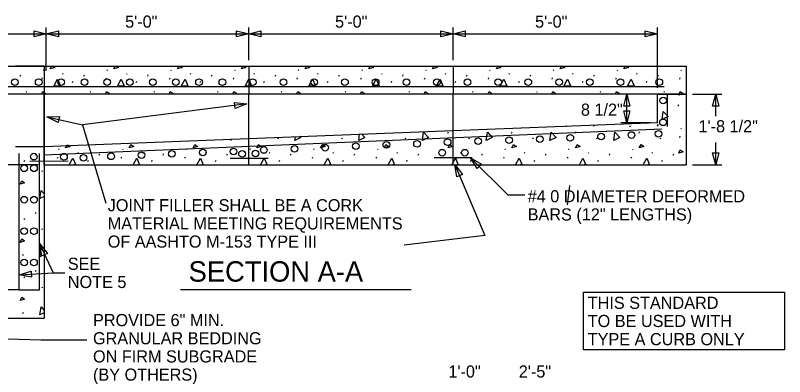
# Model space of a CAD drawing. Extents: x 100.2 to 136.1, y 126.8 to 178.4.
# Drawn here: x 116.67 to 135.49, y 144.43 to 153.28 of the extents above; entities that cross this region are included whole.
import ezdxf

# ---------------------------------------------------------------- set-up
doc = ezdxf.new("R2010")
doc.units = 0
for name, color, linetype in [('DETL-DIMS', 7, 'Continuous'), ('DETL-LINE', 7, 'Continuous'), ('DETL-NOTE', 7, 'Continuous'), ('DETL-PATT', 7, 'Continuous')]:
    doc.layers.add(name, color=color, linetype=linetype)

msp = doc.modelspace()

# ---------------------------------------------------------------- linework, layer by layer
at = {"layer": 'DETL-DIMS'}
for p, q in [((117.428, 151.919), (117.428, 152.978)), ((122.381, 152.183), (122.381, 152.978)), ((127.381, 152.183), (127.381, 152.978)), ((132.381, 151.501), (132.381, 152.978)), ((112.381, 152.83), (117.428, 152.83)), ((117.428, 152.83), (122.381, 152.83)), ((122.381, 152.83), (127.381, 152.83)), ((127.381, 152.83), (132.381, 152.83)), ((132.233, 151.353), (131.485, 151.353)), ((131.633, 150.644), (131.633, 151.353)), ((133.237, 151.353), (133.956, 151.353)), ((133.808, 150.813), (133.808, 151.353)), ((122.337, 151.11), (118.312, 150.596)), ((132.233, 150.644), (131.485, 150.644)), ((133.808, 149.618), (133.808, 150.165)), ((117.233, 149.618), (115.965, 149.618)), ((133.237, 149.618), (133.956, 149.618)), ((117.597, 146.977), (117.882, 146.977))]:
    msp.add_line(p, q, dxfattribs=at)
for points in [[(117.131, 152.904), (117.428, 152.83), (117.131, 152.756)], [(117.725, 152.756), (117.428, 152.83), (117.725, 152.904)], [(122.084, 152.904), (122.381, 152.83), (122.084, 152.756)], [(122.678, 152.756), (122.381, 152.83), (122.678, 152.904)], [(127.084, 152.904), (127.381, 152.83), (127.084, 152.756)], [(127.678, 152.756), (127.381, 152.83), (127.678, 152.904)], [(132.084, 152.904), (132.381, 152.83), (132.084, 152.756)], [(131.559, 151.056), (131.633, 151.353), (131.707, 151.056)], [(133.734, 151.056), (133.808, 151.353), (133.882, 151.056)], [(122.034, 151.145), (122.337, 151.11), (122.052, 150.999)], [(117.717, 150.656), (117.444, 150.794), (117.75, 150.8)], [(131.707, 150.941), (131.633, 150.644), (131.559, 150.941)], [(133.882, 149.915), (133.808, 149.618), (133.734, 149.915)], [(127.969, 149.53), (127.811, 149.793), (128.074, 149.635)], [(127.475, 149.326), (127.429, 149.629), (127.612, 149.384)], [(117.324, 147.389), (117.267, 147.69), (117.459, 147.451)], [(117.067, 146.869), (116.766, 146.925), (117.057, 147.017)]]:
    msp.add_lwpolyline(points, close=True, dxfattribs=at)
for points in [[(117.444, 150.794), (118.312, 150.596), (118.884, 148.681)], [(127.811, 149.793), (128.721, 148.882), (129.137, 148.882)], [(127.429, 149.629), (128.159, 147.891), (126.185, 147.654)], [(117.267, 147.69), (117.597, 146.977)], [(116.766, 146.925), (117.597, 146.977)], [(113.046, 145.468), (117.297, 145.338), (118.42, 145.338)]]:
    msp.add_lwpolyline(points, dxfattribs=at)
at = {"layer": 'DETL-LINE'}
for p, q in [((112.381, 152.035), (117.381, 152.035)), ((117.381, 152.035), (116.673, 152.035)), ((117.381, 152.035), (133.089, 152.035)), ((117.381, 152.035), (117.381, 151.353)), ((122.381, 152.035), (122.381, 151.353)), ((127.381, 152.035), (127.381, 151.353)), ((133.089, 152.035), (133.089, 149.618)), ((132.549, 151.53), (111.98, 151.53)), ((133.089, 151.353), (111.673, 151.353)), ((117.381, 149.618), (117.381, 151.353)), ((122.381, 149.618), (122.381, 151.353)), ((127.381, 149.618), (127.381, 151.353)), ((132.381, 150.644), (132.381, 151.353)), ((132.381, 151.353), (133.089, 151.353)), ((132.571, 151.353), (133.089, 151.353)), ((132.632, 150.554), (132.632, 151.351)), ((132.381, 150.644), (117.381, 150.063)), ((117.37, 149.867), (132.492, 150.503)), ((117.381, 150.063), (116.673, 150.063)), ((116.766, 146.555), (116.765, 149.893)), ((117.267, 146.555), (117.267, 149.893)), ((117.03, 149.709), (117.963, 149.716)), ((121.926, 149.78), (122.859, 149.78)), ((126.918, 149.803), (127.851, 149.803)), ((117.381, 149.618), (133.089, 149.618)), ((116.766, 146.555), (112.331, 146.555)), ((116.766, 146.555), (117.267, 146.555)), ((111.673, 145.864), (117.381, 145.864))]:
    msp.add_line(p, q, dxfattribs=at)
msp.add_lwpolyline([(111.673, 145.864), (111.673, 152.035), (117.381, 152.035), (117.381, 145.864)], dxfattribs=at)
for centre in [(116.657, 151.644), (117.243, 151.644), (117.792, 151.644), (118.362, 151.644), (118.918, 151.644), (119.475, 151.644), (120.037, 151.644), (120.601, 151.644), (121.166, 151.644), (121.737, 151.644), (122.479, 151.644), (123.232, 151.644), (123.984, 151.644), (124.737, 151.644), (125.488, 151.644), (126.241, 151.644), (126.988, 151.644), (127.737, 151.644), (128.487, 151.644), (129.223, 151.644), (129.979, 151.644), (130.728, 151.644), (131.476, 151.644), (132.429, 151.644), (132.525, 151.196), (132.52, 150.66), (131.003, 150.313), (131.749, 150.349), (132.409, 150.38), (126.5, 150.136), (127.25, 150.173), (127.997, 150.201), (128.752, 150.222), (129.504, 150.25), (130.251, 150.282), (122.01, 149.946), (122.75, 149.983), (123.504, 150.011), (124.251, 150.039), (125.002, 150.075), (125.751, 150.107), (117.122, 149.82), (117.862, 149.818), (118.341, 149.793), (119.013, 149.828), (119.758, 149.858), (120.501, 149.89), (121.257, 149.922), (122.219, 149.887), (122.55, 149.898), (127.115, 149.917), (127.671, 149.917), (116.889, 149.535), (117.128, 149.535), (116.889, 148.766), (117.128, 148.766), (116.889, 147.997), (117.128, 147.997), (116.889, 147.227), (117.128, 147.227)]:
    msp.add_circle(centre, 0.0814, dxfattribs=at)
at = {"layer": 'DETL-NOTE'}
for p, q in [((130.179, 148.644), (130.241, 149.112)), ((120.711, 146.571), (126.36, 146.571))]:
    msp.add_line(p, q, dxfattribs=at)
msp.add_lwpolyline([(130.573, 146.503), (135.495, 146.503), (135.495, 145.089), (130.573, 145.089)], close=True, dxfattribs=at)
at = {"layer": 'DETL-PATT'}
for p, q in [((117.354, 151.946), (117.366, 151.927)), ((118.914, 151.946), (118.926, 151.927)), ((120.474, 151.946), (120.486, 151.927)), ((122.034, 151.946), (122.046, 151.927)), ((123.594, 151.946), (123.606, 151.927)), ((125.154, 151.946), (125.166, 151.927)), ((126.714, 151.946), (126.726, 151.927)), ((128.274, 151.946), (128.286, 151.927)), ((129.834, 151.946), (129.846, 151.927)), ((131.394, 151.946), (131.406, 151.927)), ((132.954, 151.946), (132.966, 151.927)), ((116.79, 151.792), (116.805, 151.822)), ((117.327, 151.715), (117.339, 151.746)), ((117.828, 151.857), (117.843, 151.838)), ((118.35, 151.792), (118.365, 151.822)), ((118.887, 151.715), (118.899, 151.746)), ((119.388, 151.857), (119.403, 151.838)), ((119.91, 151.792), (119.925, 151.822)), ((120.447, 151.715), (120.459, 151.746)), ((120.948, 151.857), (120.963, 151.838)), ((121.47, 151.792), (121.485, 151.822)), ((122.007, 151.715), (122.019, 151.746)), ((122.508, 151.857), (122.523, 151.838)), ((123.03, 151.792), (123.045, 151.822)), ((123.567, 151.715), (123.579, 151.746)), ((124.068, 151.857), (124.083, 151.838)), ((124.59, 151.792), (124.605, 151.822)), ((125.127, 151.715), (125.139, 151.746)), ((125.628, 151.857), (125.643, 151.838)), ((126.15, 151.792), (126.165, 151.822)), ((126.687, 151.715), (126.699, 151.746)), ((127.188, 151.857), (127.203, 151.838)), ((127.71, 151.792), (127.725, 151.822)), ((128.247, 151.715), (128.259, 151.746)), ((128.748, 151.857), (128.763, 151.838)), ((129.27, 151.792), (129.285, 151.822)), ((129.807, 151.715), (129.819, 151.746)), ((130.308, 151.857), (130.323, 151.838)), ((130.83, 151.792), (130.845, 151.822)), ((131.367, 151.715), (131.379, 151.746)), ((131.868, 151.857), (131.883, 151.838)), ((132.39, 151.792), (132.405, 151.822)), ((132.927, 151.715), (132.939, 151.746)), ((118.072, 151.638), (118.087, 151.669)), ((119.632, 151.638), (119.647, 151.669)), ((121.192, 151.638), (121.207, 151.669)), ((122.752, 151.638), (122.767, 151.669)), ((124.312, 151.638), (124.327, 151.669)), ((125.872, 151.638), (125.887, 151.669)), ((127.432, 151.638), (127.447, 151.669)), ((128.992, 151.638), (129.007, 151.669)), ((130.552, 151.638), (130.567, 151.669)), ((132.112, 151.638), (132.127, 151.669)), ((116.94, 151.418), (116.956, 151.395)), ((118.5, 151.418), (118.516, 151.395)), ((120.06, 151.418), (120.076, 151.395)), ((121.62, 151.418), (121.636, 151.395)), ((123.18, 151.418), (123.196, 151.395)), ((124.74, 151.418), (124.756, 151.395)), ((126.3, 151.418), (126.316, 151.395)), ((127.86, 151.418), (127.876, 151.395)), ((129.42, 151.418), (129.436, 151.395)), ((130.98, 151.418), (130.996, 151.395)), ((132.54, 151.418), (132.556, 151.395)), ((132.888, 151.089), (132.892, 151.058)), ((131.704, 150.578), (131.708, 150.547)), ((125.695, 150.393), (125.697, 150.397)), ((127.255, 150.393), (127.267, 150.424)), ((128.815, 150.393), (128.827, 150.424)), ((130.147, 150.562), (130.148, 150.547)), ((130.375, 150.393), (130.387, 150.424)), ((131.935, 150.393), (131.947, 150.424)), ((132.954, 150.521), (132.966, 150.502)), ((123.097, 150.253), (123.108, 150.284)), ((124.657, 150.253), (124.668, 150.284)), ((126.217, 150.253), (126.228, 150.284)), ((127.777, 150.253), (127.788, 150.284)), ((129.337, 150.253), (129.348, 150.284)), ((130.897, 150.253), (130.908, 150.284)), ((132.457, 150.253), (132.468, 150.284)), ((132.927, 150.29), (132.939, 150.321)), ((117.166, 149.855), (117.181, 149.886)), ((117.73, 150.01), (117.742, 149.991)), ((118.204, 149.921), (118.22, 149.902)), ((118.726, 149.855), (118.741, 149.886)), ((119.29, 150.01), (119.302, 149.991)), ((119.764, 149.921), (119.78, 149.902)), ((120.286, 149.855), (120.301, 149.886)), ((120.85, 150.01), (120.862, 149.991)), ((121.324, 149.921), (121.34, 149.902)), ((121.846, 149.855), (121.861, 149.886)), ((122.41, 150.01), (122.422, 149.991)), ((122.884, 149.921), (122.9, 149.902)), ((123.406, 149.855), (123.421, 149.886)), ((123.97, 150.01), (123.982, 149.991)), ((124.444, 149.921), (124.46, 149.902)), ((124.966, 149.855), (124.981, 149.886)), ((125.53, 150.01), (125.542, 149.991)), ((126.004, 149.921), (126.02, 149.902)), ((126.526, 149.855), (126.541, 149.886)), ((127.09, 150.01), (127.102, 149.991)), ((127.564, 149.921), (127.58, 149.902)), ((128.086, 149.855), (128.101, 149.886)), ((128.65, 150.01), (128.662, 149.991)), ((129.124, 149.921), (129.14, 149.902)), ((129.646, 149.855), (129.661, 149.886)), ((130.21, 150.01), (130.222, 149.991)), ((130.684, 149.921), (130.7, 149.902)), ((131.206, 149.855), (131.221, 149.886)), ((131.77, 150.01), (131.782, 149.991)), ((132.244, 149.921), (132.26, 149.902)), ((132.766, 149.855), (132.781, 149.886)), ((116.888, 149.702), (116.903, 149.733)), ((117.703, 149.779), (117.715, 149.81)), ((118.448, 149.702), (118.463, 149.733)), ((119.263, 149.779), (119.275, 149.81)), ((120.008, 149.702), (120.023, 149.733)), ((120.823, 149.779), (120.835, 149.81)), ((121.568, 149.702), (121.583, 149.733)), ((122.383, 149.779), (122.395, 149.81)), ((123.128, 149.702), (123.143, 149.733)), ((123.943, 149.779), (123.955, 149.81)), ((124.688, 149.702), (124.703, 149.733)), ((125.503, 149.779), (125.515, 149.81)), ((126.248, 149.702), (126.263, 149.733)), ((127.063, 149.779), (127.075, 149.81)), ((127.808, 149.702), (127.823, 149.733)), ((128.623, 149.779), (128.635, 149.81)), ((129.368, 149.702), (129.383, 149.733)), ((130.183, 149.779), (130.195, 149.81)), ((130.928, 149.702), (130.943, 149.733)), ((131.743, 149.779), (131.755, 149.81)), ((132.488, 149.702), (132.503, 149.733)), ((117.317, 149.482), (117.332, 149.458)), ((116.857, 148.828), (116.868, 148.859)), ((117.166, 148.43), (117.181, 148.461)), ((116.888, 148.277), (116.903, 148.308)), ((117.317, 148.057), (117.332, 148.033)), ((116.857, 147.403), (116.868, 147.434)), ((117.166, 147.005), (117.181, 147.036)), ((116.888, 146.852), (116.903, 146.883)), ((117.317, 146.632), (117.332, 146.608)), ((116.857, 145.978), (116.868, 146.009))]:
    msp.add_line(p, q, dxfattribs=at)
for points in [[(117.523, 151.969), (117.555, 152.035)], [(117.592, 152.035), (117.635, 152.004), (117.523, 151.969)], [(119.083, 151.969), (119.115, 152.035)], [(119.152, 152.035), (119.195, 152.004), (119.083, 151.969)], [(120.643, 151.969), (120.675, 152.035)], [(120.712, 152.035), (120.755, 152.004), (120.643, 151.969)], [(122.203, 151.969), (122.235, 152.035)], [(122.272, 152.035), (122.315, 152.004), (122.203, 151.969)], [(123.763, 151.969), (123.795, 152.035)], [(123.832, 152.035), (123.875, 152.004), (123.763, 151.969)], [(125.323, 151.969), (125.355, 152.035)], [(125.392, 152.035), (125.435, 152.004), (125.323, 151.969)], [(126.883, 151.969), (126.915, 152.035)], [(126.952, 152.035), (126.995, 152.004), (126.883, 151.969)], [(128.443, 151.969), (128.475, 152.035)], [(128.512, 152.035), (128.555, 152.004), (128.443, 151.969)], [(130.003, 151.969), (130.035, 152.035)], [(130.072, 152.035), (130.115, 152.004), (130.003, 151.969)], [(131.563, 151.969), (131.595, 152.035)], [(131.632, 152.035), (131.675, 152.004), (131.563, 151.969)], [(117.612, 151.545), (117.704, 151.719), (117.774, 151.557), (117.612, 151.545)], [(119.172, 151.545), (119.264, 151.719), (119.334, 151.557), (119.172, 151.545)], [(120.732, 151.545), (120.824, 151.719), (120.894, 151.557), (120.732, 151.545)], [(122.292, 151.545), (122.384, 151.719), (122.454, 151.557), (122.292, 151.545)], [(123.852, 151.545), (123.944, 151.719), (124.014, 151.557), (123.852, 151.545)], [(125.412, 151.545), (125.504, 151.719), (125.574, 151.557), (125.412, 151.545)], [(126.972, 151.545), (127.064, 151.719), (127.134, 151.557), (126.972, 151.545)], [(128.532, 151.545), (128.624, 151.719), (128.694, 151.557), (128.532, 151.545)], [(130.092, 151.545), (130.184, 151.719), (130.254, 151.557), (130.092, 151.545)], [(131.652, 151.545), (131.744, 151.719), (131.814, 151.557), (131.652, 151.545)], [(117.315, 151.353), (117.342, 151.414), (117.412, 151.364), (117.377, 151.353)], [(118.875, 151.353), (118.902, 151.414), (118.972, 151.364), (118.937, 151.353)], [(120.435, 151.353), (120.462, 151.414), (120.532, 151.364), (120.497, 151.353)], [(121.995, 151.353), (122.022, 151.414), (122.092, 151.364), (122.057, 151.353)], [(123.555, 151.353), (123.582, 151.414), (123.652, 151.364), (123.617, 151.353)], [(125.115, 151.353), (125.142, 151.414), (125.212, 151.364), (125.177, 151.353)], [(126.675, 151.353), (126.702, 151.414), (126.772, 151.364), (126.737, 151.353)], [(128.235, 151.353), (128.262, 151.414), (128.332, 151.364), (128.297, 151.353)], [(129.795, 151.353), (129.822, 151.414), (129.892, 151.364), (129.857, 151.353)], [(131.355, 151.353), (131.382, 151.414), (131.452, 151.364), (131.417, 151.353)], [(132.904, 151.329), (132.942, 151.414), (133.012, 151.364), (132.904, 151.329)], [(132.498, 150.73), (132.525, 150.927), (132.645, 150.799), (132.498, 150.73)], [(130.827, 150.57), (130.836, 150.587)], [(132.387, 150.57), (132.406, 150.608)], [(126.634, 150.219), (126.661, 150.416), (126.781, 150.288), (126.634, 150.219)], [(128.194, 150.219), (128.221, 150.416), (128.341, 150.288), (128.194, 150.219)], [(129.754, 150.219), (129.781, 150.416), (129.901, 150.288), (129.754, 150.219)], [(131.314, 150.219), (131.341, 150.416), (131.461, 150.288), (131.314, 150.219)], [(121.954, 150.219), (121.96, 150.259)], [(123.631, 150.321), (123.661, 150.288), (123.514, 150.219)], [(123.514, 150.219), (123.528, 150.317)], [(125.138, 150.376), (125.221, 150.288), (125.074, 150.219)], [(125.074, 150.219), (125.096, 150.375)], [(117.952, 150.111), (118.011, 150.068), (117.899, 150.033)], [(117.899, 150.033), (117.937, 150.11)], [(119.459, 150.033), (119.501, 150.118), (119.571, 150.068), (119.459, 150.033)], [(121.019, 150.033), (121.061, 150.118), (121.131, 150.068), (121.019, 150.033)], [(122.579, 150.033), (122.621, 150.118), (122.691, 150.068), (122.579, 150.033)], [(124.139, 150.033), (124.181, 150.118), (124.251, 150.068), (124.139, 150.033)], [(125.699, 150.033), (125.741, 150.118), (125.811, 150.068), (125.699, 150.033)], [(127.259, 150.033), (127.301, 150.118), (127.371, 150.068), (127.259, 150.033)], [(128.819, 150.033), (128.861, 150.118), (128.931, 150.068), (128.819, 150.033)], [(130.379, 150.033), (130.421, 150.118), (130.491, 150.068), (130.379, 150.033)], [(131.939, 150.033), (131.981, 150.118), (132.051, 150.068), (131.939, 150.033)], [(132.904, 149.904), (132.942, 149.989), (133.012, 149.939), (132.904, 149.904)], [(117.992, 149.618), (118.081, 149.783), (118.15, 149.621), (118.107, 149.618)], [(119.552, 149.618), (119.641, 149.783), (119.71, 149.621), (119.667, 149.618)], [(121.112, 149.618), (121.201, 149.783), (121.27, 149.621), (121.227, 149.618)], [(122.672, 149.618), (122.761, 149.783), (122.83, 149.621), (122.787, 149.618)], [(124.232, 149.618), (124.321, 149.783), (124.39, 149.621), (124.347, 149.618)], [(125.792, 149.618), (125.881, 149.783), (125.95, 149.621), (125.907, 149.618)], [(127.352, 149.618), (127.441, 149.783), (127.51, 149.621), (127.467, 149.618)], [(128.912, 149.618), (129.001, 149.783), (129.07, 149.621), (129.027, 149.618)], [(130.472, 149.618), (130.561, 149.783), (130.63, 149.621), (130.587, 149.618)], [(132.032, 149.618), (132.121, 149.783), (132.19, 149.621), (132.147, 149.618)], [(116.787, 149.145), (116.83, 149.23), (116.895, 149.18), (116.787, 149.145)], [(117.274, 148.794), (117.301, 148.991), (117.381, 148.906)], [(117.381, 148.844), (117.274, 148.794)], [(116.787, 147.72), (116.83, 147.805), (116.895, 147.755), (116.787, 147.72)], [(117.274, 147.369), (117.301, 147.566), (117.381, 147.481)], [(117.381, 147.419), (117.274, 147.369)], [(116.787, 146.295), (116.83, 146.38), (116.895, 146.33), (116.787, 146.295)], [(117.274, 145.944), (117.301, 146.141), (117.381, 146.056)], [(117.381, 145.994), (117.274, 145.944)]]:
    msp.add_lwpolyline(points, dxfattribs=at)

# ---------------------------------------------------------------- texts
at = {"layer": 'DETL-NOTE'}
for s, height, p in [('5\'-0"', 0.297, (119.358, 152.978)), ('5\'-0"', 0.297, (124.495, 152.978)), ('5\'-0"', 0.297, (129.389, 152.978)), ('8 1/2"', 0.297, (130.511, 150.822)), ('1\'-8 1/2"', 0.297, (133.388, 150.416)), ('#4 0 DIAMETER DEFORMED ', 0.297, (129.208, 148.702)), ('JOINT FILLER SHALL BE A CORK', 0.297, (118.932, 148.482)), ('BARS (12" LENGTHS)', 0.297, (129.208, 148.257)), ('MATERIAL MEETING REQUIREMENTS', 0.297, (118.932, 148.037)), ('OF AASHTO M-153 TYPE III', 0.297, (118.932, 147.592)), ('SEE ', 0.297, (117.955, 147.048)), ('SECTION A-A', 0.5, (120.911, 146.759)), ('NOTE 5 ', 0.297, (117.955, 146.603)), ('THIS STANDARD', 0.297, (130.677, 146.093)), ('PROVIDE 6" MIN.', 0.297, (118.572, 145.67)), ('TO BE USED WITH', 0.297, (130.677, 145.648)), ('GRANULAR BEDDING', 0.297, (118.572, 145.225)), ('TYPE A CURB ONLY', 0.297, (130.677, 145.203)), ('ON FIRM SUBGRADE', 0.297, (118.572, 144.78)), ('(BY OTHERS)', 0.297, (118.572, 144.335)), ('1\'-0"', 0.297, (127.267, 144.411)), ('2\'-5"', 0.297, (128.99, 144.411))]:
    msp.add_text(s, height=height, dxfattribs=at).set_placement(p)

doc.saveas('drawing.dxf')
